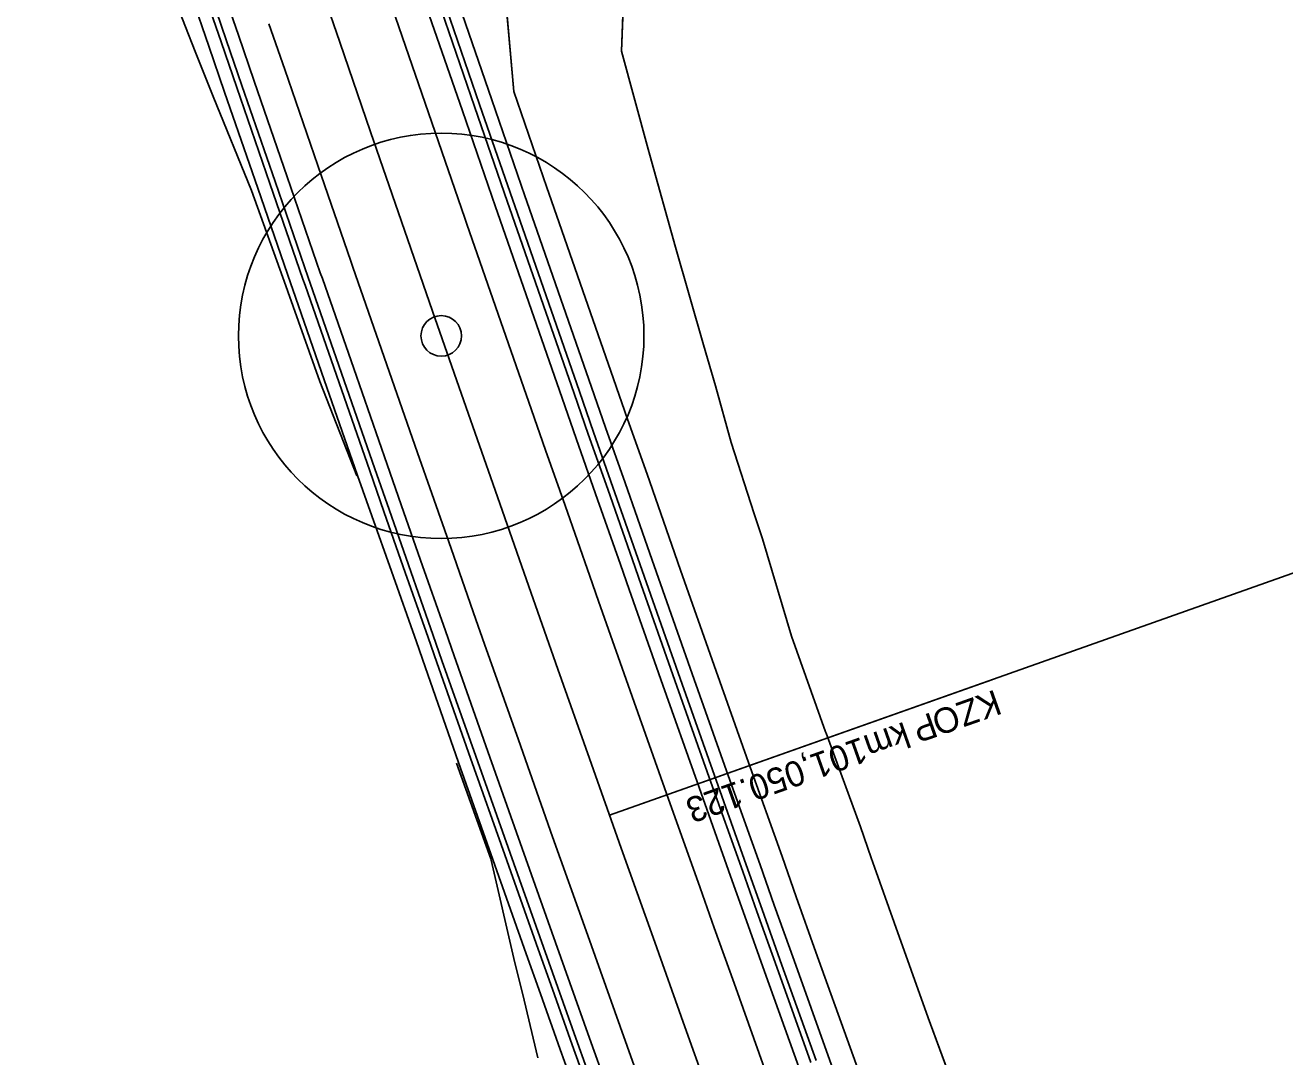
# Model space of a CAD drawing. Extents: x -678487 to -674601, y -1104811 to -1093295.
# Drawn here: x -677039.7 to -676915.5, y -1097813.6 to -1097711.9 of the extents above; entities that cross this region are included whole.
import ezdxf

# ---------------------------------------------------------------- set-up
doc = ezdxf.new("R2010")
doc.units = 0
for name, color, linetype in [('SOxxxxxx_Koleje_LN_staničení_zaoblení_Popis', 7, 'Continuous'), ('SOxxxxxx_Koleje_LN_staničení_zaoblení_Popis10', 7, 'Continuous'), ('SOxxxxxx_Osa_bod_P', 7, 'Continuous'), ('SOxxxxxx_Staničení_Popis', 7, 'Continuous'), ('SOxxxxxx_Staničení_Popis10', 7, 'Continuous'), ('SOxxxxxx_ŽSp_hrana', 7, 'Continuous'), ('SOxxxxxx_ŽSp_odvodnění', 7, 'Continuous'), ('SOxxxxxx_ŽSp_zářez_hrana', 7, 'Continuous'), ('SOxxxxxx_ŽSp_zářez_plocha', 7, 'Continuous')]:
    doc.layers.add(name, color=color, linetype=linetype)

msp = doc.modelspace()

# ---------------------------------------------------------------- linework, layer by layer
at = {"layer": 'SOxxxxxx_Koleje_LN_staničení_zaoblení_Popis'}
msp.add_line((-676982.07, -1097789.79), (-676944.37, -1097776.42), dxfattribs=at)
at = {"layer": 'SOxxxxxx_Koleje_LN_staničení_zaoblení_Popis10'}
msp.add_line((-676982.07, -1097789.79), (-676605.06, -1097656.12), dxfattribs=at)
at = {"layer": 'SOxxxxxx_Osa_bod_P'}
msp.add_arc((-668968.6, -1094948.57), 8502.25, 183.991255, 200.113006, dxfattribs=at)
at = {"layer": 'SOxxxxxx_Staničení_Popis'}
msp.add_line((-676998.68, -1097742.5), (-676998.68, -1097742.5), dxfattribs=at)
msp.add_circle((-676998.68, -1097742.5), 2, dxfattribs=at)
at = {"layer": 'SOxxxxxx_Staničení_Popis10'}
msp.add_line((-676998.68, -1097742.5), (-676998.68, -1097742.5), dxfattribs=at)
msp.add_circle((-676998.68, -1097742.5), 20, dxfattribs=at)
at = {"layer": 'SOxxxxxx_ŽSp_hrana'}
for p, q in [((-677004.43, -1097707.48), (-677002.87, -1097712)), ((-677015.68, -1097711.71), (-677014.12, -1097716.23)), ((-677002.87, -1097712), (-676999.61, -1097721.45)), ((-677014.12, -1097716.23), (-677010.86, -1097725.69)), ((-676999.61, -1097721.45), (-676996.35, -1097730.9)), ((-677010.86, -1097725.69), (-677007.59, -1097735.14)), ((-676996.35, -1097730.9), (-676996.15, -1097731.47)), ((-676996.15, -1097731.47), (-676993.07, -1097740.35)), ((-677007.59, -1097735.14), (-677007.4, -1097735.71)), ((-677007.4, -1097735.71), (-677004.31, -1097744.59)), ((-676993.07, -1097740.35), (-676989.77, -1097749.79)), ((-677004.31, -1097744.59), (-677001.02, -1097754.04)), ((-676989.77, -1097749.79), (-676988.38, -1097753.78)), ((-676988.38, -1097753.78), (-676986.47, -1097759.23)), ((-677001.02, -1097754.04), (-676999.62, -1097758.04)), ((-676999.62, -1097758.04), (-676997.71, -1097763.48)), ((-676986.47, -1097759.23), (-676984.02, -1097766.21)), ((-676997.71, -1097763.48), (-676995.26, -1097770.47)), ((-676984.02, -1097766.21), (-676983.16, -1097768.66)), ((-676983.16, -1097768.66), (-676979.83, -1097778.09)), ((-676995.26, -1097770.47), (-676994.4, -1097772.92)), ((-676994.4, -1097772.92), (-676991.07, -1097782.36)), ((-676979.83, -1097778.09), (-676976.45, -1097787.65)), ((-676991.07, -1097782.36), (-676987.69, -1097791.92)), ((-676976.45, -1097787.65), (-676973.15, -1097796.95)), ((-676987.69, -1097791.92), (-676984.39, -1097801.21)), ((-676973.15, -1097796.95), (-676971.74, -1097800.9)), ((-676971.74, -1097800.9), (-676969.79, -1097806.37)), ((-676984.39, -1097801.21), (-676982.98, -1097805.17)), ((-676982.98, -1097805.17), (-676981.03, -1097810.64)), ((-676969.79, -1097806.37), (-676966.42, -1097815.78)), ((-676981.03, -1097810.64), (-676977.66, -1097820.05))]:
    msp.add_line(p, q, dxfattribs=at)
at = {"layer": 'SOxxxxxx_ŽSp_odvodnění'}
for p, q in [((-677022.1, -1097708.54), (-677020.4, -1097713.48)), ((-677021.59, -1097708.35), (-677019.89, -1097713.29)), ((-676998.15, -1097710.22), (-676994.89, -1097719.67)), ((-676998.66, -1097710.41), (-676995.4, -1097719.86)), ((-677020.4, -1097713.48), (-677018.85, -1097718.01)), ((-677019.89, -1097713.29), (-677018.34, -1097717.81)), ((-677018.85, -1097718.01), (-677015.59, -1097727.47)), ((-677018.34, -1097717.81), (-677015.07, -1097727.27)), ((-676995.4, -1097719.86), (-676992.14, -1097729.31)), ((-676994.89, -1097719.67), (-676991.62, -1097729.12)), ((-677015.59, -1097727.47), (-677012.32, -1097736.92)), ((-677015.07, -1097727.27), (-677011.8, -1097736.73)), ((-676992.14, -1097729.31), (-676991.94, -1097729.88)), ((-676991.94, -1097729.88), (-676988.86, -1097738.76)), ((-676991.62, -1097729.12), (-676991.42, -1097729.68)), ((-676991.42, -1097729.68), (-676988.34, -1097738.56)), ((-677012.32, -1097736.92), (-677012.12, -1097737.49)), ((-677012.12, -1097737.49), (-677009.03, -1097746.38)), ((-677011.8, -1097736.73), (-677011.61, -1097737.3)), ((-677011.61, -1097737.3), (-677008.52, -1097746.18)), ((-676988.86, -1097738.76), (-676985.57, -1097748.2)), ((-676988.34, -1097738.56), (-676985.05, -1097748)), ((-677008.52, -1097746.18), (-677005.23, -1097755.63)), ((-677009.03, -1097746.38), (-677005.74, -1097755.83)), ((-676985.57, -1097748.2), (-676984.17, -1097752.19)), ((-676985.05, -1097748), (-676983.66, -1097751.99)), ((-676984.17, -1097752.19), (-676982.26, -1097757.63)), ((-676983.66, -1097751.99), (-676981.75, -1097757.44)), ((-677005.74, -1097755.83), (-677004.34, -1097759.82)), ((-677005.23, -1097755.63), (-677003.83, -1097759.63)), ((-676981.75, -1097757.44), (-676979.3, -1097764.42)), ((-676982.26, -1097757.63), (-676979.81, -1097764.61)), ((-677004.34, -1097759.82), (-677002.44, -1097765.27)), ((-677003.83, -1097759.63), (-677001.92, -1097765.08)), ((-676979.81, -1097764.61), (-676978.95, -1097767.07)), ((-676979.3, -1097764.42), (-676978.44, -1097766.87)), ((-677002.44, -1097765.27), (-676999.98, -1097772.26)), ((-677001.92, -1097765.08), (-676999.47, -1097772.06)), ((-676978.95, -1097767.07), (-676975.63, -1097776.5)), ((-676978.44, -1097766.87), (-676975.11, -1097776.3)), ((-676999.98, -1097772.26), (-676999.12, -1097774.71)), ((-676999.47, -1097772.06), (-676998.61, -1097774.52)), ((-676999.12, -1097774.71), (-676995.79, -1097784.15)), ((-676998.61, -1097774.52), (-676995.28, -1097783.95)), ((-676975.63, -1097776.5), (-676972.24, -1097786.06)), ((-676975.11, -1097776.3), (-676971.73, -1097785.86)), ((-676995.79, -1097784.15), (-676992.41, -1097793.71)), ((-676995.28, -1097783.95), (-676991.89, -1097793.52)), ((-676972.24, -1097786.06), (-676968.94, -1097795.35)), ((-676971.73, -1097785.86), (-676968.43, -1097795.15)), ((-676991.89, -1097793.52), (-676988.59, -1097802.81)), ((-676992.41, -1097793.71), (-676989.11, -1097803.01)), ((-676968.94, -1097795.35), (-676967.53, -1097799.3)), ((-676968.43, -1097795.15), (-676967.02, -1097799.1)), ((-676967.53, -1097799.3), (-676965.58, -1097804.77)), ((-676967.02, -1097799.1), (-676965.07, -1097804.57)), ((-676989.11, -1097803.01), (-676987.7, -1097806.96)), ((-676988.59, -1097802.81), (-676987.18, -1097806.77)), ((-676965.58, -1097804.77), (-676962.22, -1097814.18)), ((-676965.07, -1097804.57), (-676961.7, -1097813.99)), ((-676987.7, -1097806.96), (-676985.75, -1097812.43)), ((-676987.18, -1097806.77), (-676985.23, -1097812.24)), ((-676985.23, -1097812.24), (-676981.86, -1097821.65)), ((-676985.75, -1097812.43), (-676982.38, -1097821.85))]:
    msp.add_line(p, q, dxfattribs=at)
at = {"layer": 'SOxxxxxx_ŽSp_zářez_hrana'}
for p, q in [((-676980.47, -1097703.57), (-676980.91, -1097714.4)), ((-677023.3, -1097708.99), (-677021.6, -1097713.93)), ((-677020.39, -1097707.9), (-677018.69, -1097712.84)), ((-676992.44, -1097708.07), (-676991.52, -1097718.4)), ((-677024.86, -1097709.58), (-677022.97, -1097714.45)), ((-676996.95, -1097709.77), (-676993.69, -1097719.22)), ((-676999.86, -1097710.86), (-676996.6, -1097720.31)), ((-677021.6, -1097713.93), (-677020.05, -1097718.46)), ((-677018.69, -1097712.84), (-677017.14, -1097717.36)), ((-677022.97, -1097714.45), (-677021.19, -1097718.89)), ((-676980.91, -1097714.4), (-676978.26, -1097724.08)), ((-677017.14, -1097717.36), (-677013.88, -1097726.82)), ((-677021.19, -1097718.89), (-677017.4, -1097728.15)), ((-677020.05, -1097718.46), (-677016.79, -1097727.92)), ((-676991.52, -1097718.4), (-676988.25, -1097727.85)), ((-676993.69, -1097719.22), (-676990.42, -1097728.67)), ((-676996.6, -1097720.31), (-676993.33, -1097729.76)), ((-676978.26, -1097724.08), (-676978.1, -1097724.66)), ((-676978.1, -1097724.66), (-676975.57, -1097733.74)), ((-677013.88, -1097726.82), (-677010.61, -1097736.28)), ((-677017.4, -1097728.15), (-677014.01, -1097737.56)), ((-677016.79, -1097727.92), (-677013.51, -1097737.38)), ((-676990.42, -1097728.67), (-676990.23, -1097729.23)), ((-676988.25, -1097727.85), (-676988.06, -1097728.41)), ((-676988.06, -1097728.41), (-676984.97, -1097737.29)), ((-676993.33, -1097729.76), (-676993.14, -1097730.33)), ((-676990.23, -1097729.23), (-676987.14, -1097738.11)), ((-676993.14, -1097730.33), (-676990.05, -1097739.21)), ((-676975.57, -1097733.74), (-676972.82, -1097743.37)), ((-677010.61, -1097736.28), (-677010.41, -1097736.85)), ((-677014.01, -1097737.56), (-677013.82, -1097738.13)), ((-677013.51, -1097737.38), (-677013.32, -1097737.94)), ((-677010.41, -1097736.85), (-677007.32, -1097745.73)), ((-676984.97, -1097737.29), (-676981.68, -1097746.73)), ((-677013.82, -1097738.13), (-677010.65, -1097746.99)), ((-677013.32, -1097737.94), (-677010.23, -1097746.83)), ((-676987.14, -1097738.11), (-676983.85, -1097747.55)), ((-676990.05, -1097739.21), (-676986.76, -1097748.65)), ((-676972.82, -1097743.37), (-676971.61, -1097747.44)), ((-677007.32, -1097745.73), (-677004.03, -1097755.18)), ((-677010.65, -1097746.99), (-677007.01, -1097756.31)), ((-677010.23, -1097746.83), (-677006.94, -1097756.28)), ((-676983.85, -1097747.55), (-676982.46, -1097751.54)), ((-676981.68, -1097746.73), (-676980.29, -1097750.72)), ((-676971.61, -1097747.44), (-676970.08, -1097753.02)), ((-676986.76, -1097748.65), (-676985.37, -1097752.64)), ((-676980.29, -1097750.72), (-676978.38, -1097756.16)), ((-676982.46, -1097751.54), (-676980.55, -1097756.99)), ((-676985.37, -1097752.64), (-676983.46, -1097758.09)), ((-676970.08, -1097753.02), (-676967.8, -1097760.06)), ((-677006.94, -1097756.28), (-677005.54, -1097760.27)), ((-677004.03, -1097755.18), (-677002.63, -1097759.18)), ((-676978.38, -1097756.16), (-676975.93, -1097763.14)), ((-676980.55, -1097756.99), (-676978.1, -1097763.96)), ((-676983.46, -1097758.09), (-676981.01, -1097765.07)), ((-677002.63, -1097759.18), (-677000.72, -1097764.62)), ((-677005.54, -1097760.27), (-677003.6, -1097765.71)), ((-676967.8, -1097760.06), (-676966.99, -1097762.53)), ((-676975.93, -1097763.14), (-676975.07, -1097765.6)), ((-676966.99, -1097762.53), (-676964.14, -1097772.14)), ((-677000.72, -1097764.62), (-676998.27, -1097771.61)), ((-676978.1, -1097763.96), (-676977.24, -1097766.42)), ((-677003.6, -1097765.71), (-677001.13, -1097772.69)), ((-676981.01, -1097765.07), (-676980.15, -1097767.52)), ((-676975.07, -1097765.6), (-676971.75, -1097775.03)), ((-676977.24, -1097766.42), (-676973.91, -1097775.85)), ((-676980.15, -1097767.52), (-676976.82, -1097776.95)), ((-676998.27, -1097771.61), (-676997.41, -1097774.06)), ((-676964.14, -1097772.14), (-676960.76, -1097781.55)), ((-677001.13, -1097772.69), (-677000.27, -1097775.15)), ((-676997.41, -1097774.06), (-676994.08, -1097783.5)), ((-677000.27, -1097775.15), (-676996.99, -1097784.6)), ((-676973.91, -1097775.85), (-676970.53, -1097785.41)), ((-676971.75, -1097775.03), (-676968.36, -1097784.58)), ((-676976.82, -1097776.95), (-676973.44, -1097786.51)), ((-676960.76, -1097781.55), (-676960.71, -1097781.68)), ((-676960.71, -1097781.68), (-676957.33, -1097790.93)), ((-676994.08, -1097783.5), (-676990.7, -1097793.06)), ((-676997.18, -1097784.67), (-676993.8, -1097794.09)), ((-676996.99, -1097784.6), (-676993.6, -1097794.17)), ((-676968.36, -1097784.58), (-676965.06, -1097793.87)), ((-676970.53, -1097785.41), (-676967.23, -1097794.7)), ((-676973.44, -1097786.51), (-676970.14, -1097795.8)), ((-676957.33, -1097790.93), (-676956.27, -1097794)), ((-676990.7, -1097793.06), (-676987.4, -1097802.36)), ((-676993.8, -1097794.09), (-676993.75, -1097794.22)), ((-676993.75, -1097794.22), (-676991.52, -1097803.92)), ((-676993.6, -1097794.17), (-676990.3, -1097803.46)), ((-676967.23, -1097794.7), (-676965.82, -1097798.65)), ((-676965.06, -1097793.87), (-676963.66, -1097797.83)), ((-676956.27, -1097794), (-676955.95, -1097794.9)), ((-676970.14, -1097795.8), (-676968.73, -1097799.75)), ((-676955.95, -1097794.9), (-676954.01, -1097800.36)), ((-676963.66, -1097797.83), (-676961.71, -1097803.29)), ((-676968.73, -1097799.75), (-676966.78, -1097805.22)), ((-676965.82, -1097798.65), (-676963.87, -1097804.12)), ((-676954.01, -1097800.36), (-676950.65, -1097809.78)), ((-676990.3, -1097803.46), (-676988.89, -1097807.42)), ((-676987.4, -1097802.36), (-676985.99, -1097806.31)), ((-676961.71, -1097803.29), (-676958.34, -1097812.71)), ((-676991.52, -1097803.92), (-676990.51, -1097808.03)), ((-676963.87, -1097804.12), (-676960.5, -1097813.53)), ((-676966.78, -1097805.22), (-676963.41, -1097814.64)), ((-676985.99, -1097806.31), (-676984.04, -1097811.78)), ((-676990.51, -1097808.03), (-676989.16, -1097813.73)), ((-676988.89, -1097807.42), (-676986.94, -1097812.89)), ((-676950.65, -1097809.78), (-676947.18, -1097819.16)), ((-676984.04, -1097811.78), (-676980.67, -1097821.2)), ((-676986.94, -1097812.89), (-676983.57, -1097822.3)), ((-676958.34, -1097812.71), (-676954.96, -1097822.12)), ((-676960.5, -1097813.53), (-676957.12, -1097822.94))]:
    msp.add_line(p, q, dxfattribs=at)
at = {"layer": 'SOxxxxxx_ŽSp_zářez_plocha'}
for points in [[(-676980.47, -1097703.57), (-676980.91, -1097714.4), (-676978.26, -1097724.08), (-676978.1, -1097724.66), (-676975.57, -1097733.74), (-676972.82, -1097743.37), (-676971.61, -1097747.44), (-676970.08, -1097753.02), (-676967.8, -1097760.06), (-676966.99, -1097762.53), (-676964.14, -1097772.14), (-676960.76, -1097781.55), (-676960.71, -1097781.68), (-676957.33, -1097790.93), (-676956.27, -1097794), (-676955.95, -1097794.9), (-676954.01, -1097800.36), (-676950.65, -1097809.78), (-676947.18, -1097819.16)], [(-676954.96, -1097822.12), (-676958.34, -1097812.71), (-676961.71, -1097803.29), (-676963.66, -1097797.83), (-676965.06, -1097793.87), (-676968.36, -1097784.58), (-676971.75, -1097775.03), (-676975.07, -1097765.6), (-676975.93, -1097763.14), (-676978.38, -1097756.16), (-676980.29, -1097750.72), (-676981.68, -1097746.73), (-676984.97, -1097737.29), (-676988.06, -1097728.41), (-676988.25, -1097727.85), (-676991.52, -1097718.4), (-676992.44, -1097708.07)]]:
    msp.add_lwpolyline(points, dxfattribs=at)

# ---------------------------------------------------------------- texts
at = {"layer": 'SOxxxxxx_Koleje_LN_staničení_zaoblení_Popis'}
for s, p in [('KZO', (-676944.03, -1097777.36)), ('P', (-676950.33, -1097779.6)), (' km ', (-676952.13, -1097780.23)), ('101,050.123', (-676957.23, -1097782.04))]:
    msp.add_text(s, height=2.5, rotation=199.5222, dxfattribs=at).set_placement(p)

doc.saveas('drawing.dxf')
